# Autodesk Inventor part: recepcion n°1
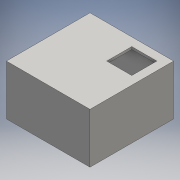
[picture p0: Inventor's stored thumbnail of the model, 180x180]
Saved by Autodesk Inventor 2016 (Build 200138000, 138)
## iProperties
Created: 2016-06
Part Number: recepcion n°1
Material: Genérico
Document SubType Name: Modeling
Designer: adm
Density: 1 g/cm^3
Appearance: Valor por defecto
Author: adm
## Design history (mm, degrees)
sketch "Boceto1"
  geometry: L1 (-50, -50)-(50, -50); L2 (50, -50)-(50, 50); L3 (50, 50)-(-50, 50); L4 (-50, 50)-(-50, -50); L5 (-50, -50)-(50, 50); L6 (50, -50)-(-50, 50); 1 further point
  constraints: 12 end point, 2 midpoint, 2 parallel, 1 horizontal, 1 perpendicular
  dimensions: "d0" = 100 distance of L3.end L2.end; "d1" = 100 distance of L2.end L1.end
extrude "Extrusión1" new body sketch "Boceto1" distance "d2" = 60; taper "d3" = 0 deg
feature "Vaciado1" dims "d4" = 3
sketch "Boceto2"
  geometry: L1 (-50, 50)-(-50, -50) reference; L2 (50, -50)-(-50, -50); L3 (-50, -50)-(-50, 50); L4 (-50, 50)-(50, 50); L5 (50, 50)-(50, -50); L6 (10, 10)-(40, 10); L7 (40, 10)-(40, 40); L8 (40, 40)-(10, 40); L9 (10, 40)-(10, 10); L10 (10, 10)-(40, 40); L11 (40, 10)-(10, 40); 2 further points
  constraints: 20 end point, 4 parallel, 2 horizontal, 2 midpoint, 2 perpendicular
  dimensions: "d5" = 30 distance of L8.end L7.end; "d6" = 30 distance of L7.end L6.end; "d7" = 25 distance from line of point (25, 25) L4; "d8" = 25 distance from line of L5 point (25, 25); "d9" = 100 distance between parallel lines of L5 L1; "d10" = 100 distance between parallel lines of L2 L4
extrude "Extrusión2" join sketch "Boceto2" distance "d11" = 3; taper "d12" = 0 deg
sketch "Boceto4"
  geometry: L1 (0, 100)-(60, 100) reference; L2 (5.092, 91.382)-(15.092, 91.382); L3 (15.092, 91.382)-(15.092, 81.382); L4 (15.092, 81.382)-(5.092, 81.382); L5 (5.092, 81.382)-(5.092, 91.382); 2 further points
  constraints: 8 end point, 2 parallel, 1 coincident, 1 horizontal, 1 perpendicular
  dimensions: "d19" = 10 distance of L3.end L4.end; "d20" = 10 distance of L2.end L3.end
extrude "Extrusión4" cut sketch "Boceto4" distance "d21" = 10; taper "d22" = 0 deg
node "Sólido1"
